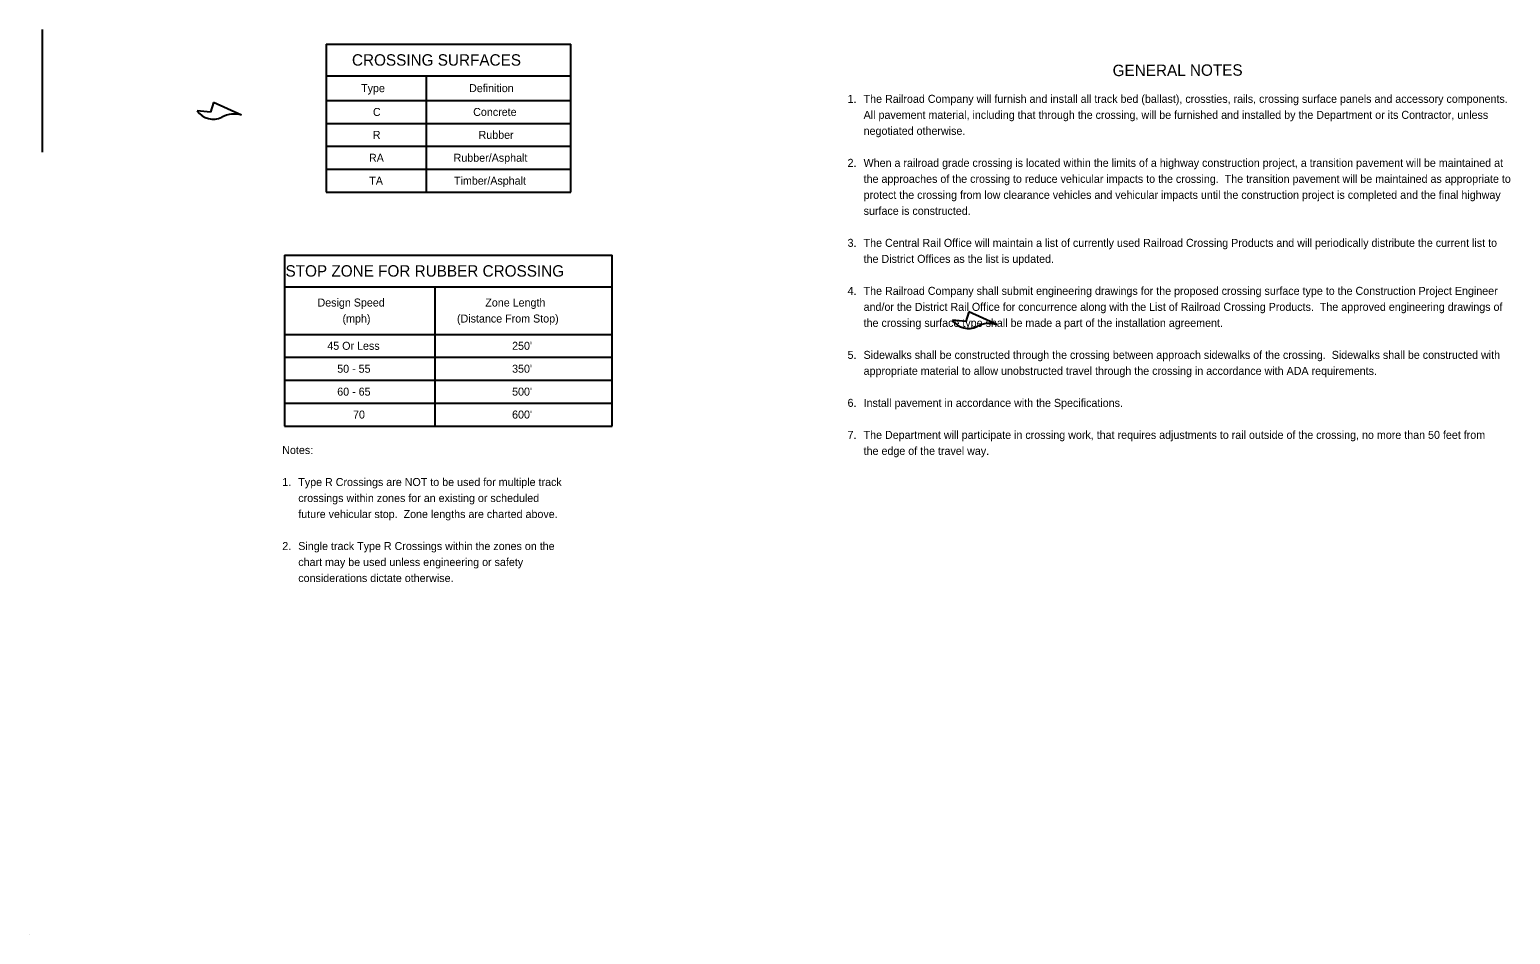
# Model space of a CAD drawing. Extents: x 10000 to 10648, y 10000 to 10396.
import ezdxf

# ---------------------------------------------------------------- set-up
doc = ezdxf.new("R2010")
doc.units = 0
for name, color, linetype in [('Default', 7, 'Continuous'), ('Dimension', 7, 'Continuous'), ('Patterning', 7, 'Continuous'), ('SupstrConc', 7, 'Continuous'), ('TextMisc', 7, 'Continuous')]:
    doc.layers.add(name, color=color, linetype=linetype)

msp = doc.modelspace()

# ---------------------------------------------------------------- linework, layer by layer
at = {"layer": 'Default'}
msp.add_line((10000, 10000), (10000, 10000), dxfattribs=at)
msp.add_line((10000, 10000), (10000, 10000), dxfattribs=at)
msp.add_line((10000, 10000), (10000, 10000), dxfattribs=at)
msp.add_line((10000, 10000), (10000, 10000), dxfattribs=at)
msp.add_line((10000, 10000), (10000, 10000), dxfattribs=at)
msp.add_line((10000, 10000), (10000, 10000), dxfattribs=at)
msp.add_line((10000, 10000), (10000, 10000), dxfattribs=at)
msp.add_line((10000, 10000), (10000, 10000), dxfattribs=at)
msp.add_line((10000, 10000), (10000, 10000), dxfattribs=at)
msp.add_line((10000, 10000), (10000, 10000), dxfattribs=at)
msp.add_line((10000, 10000), (10000, 10000), dxfattribs=at)
msp.add_line((10000, 10000), (10000, 10000), dxfattribs=at)
msp.add_line((10000, 10000), (10000, 10000), dxfattribs=at)
msp.add_line((10000, 10000), (10000, 10000), dxfattribs=at)
msp.add_line((10000, 10000), (10000, 10000), dxfattribs=at)
msp.add_line((10000, 10000), (10000, 10000), dxfattribs=at)
msp.add_line((10000, 10000), (10000, 10000), dxfattribs=at)
msp.add_line((10000, 10000), (10000, 10000), dxfattribs=at)
msp.add_line((10000, 10000), (10000, 10000), dxfattribs=at)
msp.add_line((10000, 10000), (10000, 10000), dxfattribs=at)
msp.add_line((10000, 10000), (10000, 10000), dxfattribs=at)
at = {"layer": 'Dimension'}
for p, q in [((10080.45, 10363.99), (10079.11, 10359.65)), ((10092.65, 10358.31), (10080.45, 10363.99)), ((10079.11, 10359.65), (10073.32, 10360.29)), ((10410.8, 10272.41), (10409.46, 10268.06)), ((10422.99, 10266.73), (10410.8, 10272.41)), ((10409.46, 10268.06), (10403.67, 10268.7))]:
    msp.add_line(p, q, dxfattribs=at)
for centre, radius, start, end in [((10080.41, 10365.34), 8.7, 215.52054, 295.31839), ((10089.31, 10348.47), 10.39, 71.2682, 119.91924), ((10410.75, 10273.76), 8.7, 215.52054, 295.31839), ((10419.66, 10256.88), 10.39, 71.2682, 119.91924)]:
    msp.add_arc(centre, radius, start, end, dxfattribs=at)
at = {"layer": 'Patterning'}
msp.add_line((10000, 10000), (10000, 10000), dxfattribs=at)
at = {"layer": 'SupstrConc'}
for p, q in [((10129.64, 10389.45), (10129.64, 10324.71)), ((10129.64, 10389.45), (10236.63, 10389.45)), ((10236.63, 10324.74), (10236.63, 10389.45)), ((10129.64, 10375.62), (10173.64, 10375.62)), ((10173.64, 10324.71), (10173.64, 10375.62)), ((10173.64, 10375.62), (10236.63, 10375.62)), ((10129.64, 10364.78), (10236.63, 10364.78)), ((10129.64, 10354.78), (10236.63, 10354.78)), ((10129.64, 10344.76), (10236.63, 10344.76)), ((10129.64, 10334.73), (10236.63, 10334.73)), ((10129.64, 10324.71), (10236.63, 10324.71)), ((10111.52, 10297.16), (10111.52, 10222.39)), ((10111.52, 10297.16), (10254.74, 10297.16)), ((10254.74, 10222.39), (10254.74, 10297.16)), ((10111.52, 10283.33), (10177.36, 10283.33)), ((10177.36, 10283.33), (10254.74, 10283.33)), ((10177.36, 10222.39), (10177.36, 10283.33)), ((10111.52, 10262.49), (10254.74, 10262.49)), ((10111.52, 10252.47), (10254.74, 10252.47)), ((10111.52, 10242.44), (10254.74, 10242.44)), ((10111.52, 10232.42), (10254.74, 10232.42)), ((10111.52, 10222.39), (10254.74, 10222.39))]:
    msp.add_line(p, q, dxfattribs=at)
at = {"layer": 'TextMisc'}
msp.add_line((10005.67, 10342.13), (10005.67, 10395.81), dxfattribs=at)

# ---------------------------------------------------------------- texts
for s, height, p in [('CROSSING SURFACES', 5, (10140.98, 10380.03)), ('Type', 3.5, (10144.98, 10368.45)), ('Definition', 3.5, (10192.19, 10368.45)), ('1.', 3.5, (10357.73, 10363.77)), ('The Railroad Company will furnish and install all track bed (ballast), crossties, rails, crossing surface panels and accessory components.  ', 3.5, (10364.73, 10363.77)), ('C', 3.5, (10150.15, 10358.03)), ('Concrete', 3.5, (10193.99, 10358.03)), ('All pavement material, including that through the crossing, will be furnished and installed by the Department or its Contractor, unless ', 3.5, (10364.75, 10356.77)), ('R', 3.5, (10150.07, 10348.02)), ('Rubber', 3.5, (10196.34, 10348.02)), ('negotiated otherwise.   ', 3.5, (10364.75, 10349.77)), ('RA', 3.5, (10148.42, 10338)), ('Rubber/Asphalt', 3.5, (10185.43, 10338)), ('2.', 3.5, (10357.73, 10335.77)), ('When a railroad grade crossing is located within the limits of a highway construction project, a transition pavement will be maintained at ', 3.5, (10364.73, 10335.77)), ('TA', 3.5, (10148.54, 10327.97)), ('Timber/Asphalt', 3.5, (10185.61, 10327.97)), ('the approaches of the crossing to reduce vehicular impacts to the crossing.  The transition pavement will be maintained as appropriate to ', 3.5, (10364.75, 10328.77)), ('protect the crossing from low clearance vehicles and vehicular impacts until the construction project is completed and the final highway ', 3.5, (10364.75, 10321.77)), ('surface is constructed.  ', 3.5, (10364.75, 10314.77)), ('3.', 3.5, (10357.73, 10300.77)), ('The Central Rail Office will maintain a list of currently used Railroad Crossing Products and will periodically distribute the current list to ', 3.5, (10364.73, 10300.77)), ('the District Offices as the list is updated.   ', 3.5, (10364.75, 10293.77)), ('STOP ZONE FOR RUBBER CROSSING', 5, (10111.92, 10287.74)), ('Design Speed', 3.5, (10125.91, 10274.66)), ('Zone Length', 3.5, (10199.29, 10274.66)), ('4.', 3.5, (10357.73, 10279.77)), ('The Railroad Company shall submit engineering drawings for the proposed crossing surface type to the Construction Project Engineer ', 3.5, (10364.73, 10279.77)), ('(mph)', 3.5, (10136.85, 10267.66)), ('(Distance From Stop)', 3.5, (10186.9, 10267.66)), ('and/or the District Rail Office for concurrence along with the List of Railroad Crossing Products.  The approved engineering drawings of ', 3.5, (10364.75, 10272.77)), ('the crossing surface type shall be made a part of the installation agreement.   ', 3.5, (10364.75, 10265.77)), ('45 Or Less', 3.5, (10130.19, 10255.73)), ("250'", 3.5, (10211.01, 10255.73)), ('5.', 3.5, (10357.73, 10251.77)), ('Sidewalks shall be constructed through the crossing between approach sidewalks of the crossing.  Sidewalks shall be constructed with ', 3.5, (10364.73, 10251.77)), ('50 - 55', 3.5, (10134.53, 10245.7)), ("350'", 3.5, (10211.01, 10245.7)), ('appropriate material to allow unobstructed travel through the crossing in accordance with ADA requirements.   ', 3.5, (10364.75, 10244.77)), ('60 - 65', 3.5, (10134.53, 10235.68)), ("500'", 3.5, (10211.01, 10235.68)), ('6.', 3.5, (10357.73, 10230.77)), ('Install pavement in accordance with the Specifications. ', 3.5, (10364.73, 10230.77)), ('70', 3.5, (10141.44, 10225.65)), ("600'", 3.5, (10211.01, 10225.65)), ('7.', 3.5, (10357.73, 10216.77)), ('The Department will participate in crossing work, that requires adjustments to rail outside of the crossing, no more than 50 feet from ', 3.5, (10364.73, 10216.77)), ('Notes:', 3.5, (10110.49, 10210.14)), ('the edge of the travel way.', 3.5, (10364.75, 10209.77)), ('1.', 3.5, (10110.49, 10196.14)), ('Type R Crossings are NOT to be used for multiple track ', 3.5, (10117.49, 10196.14)), ('crossings within zones for an existing or scheduled ', 3.5, (10117.5, 10189.14)), ('future vehicular stop.  Zone lengths are charted above.', 3.5, (10117.5, 10182.14)), ('2.', 3.5, (10110.49, 10168.14)), ('Single track Type R Crossings within the zones on the ', 3.5, (10117.49, 10168.14)), ('chart may be used unless engineering or safety ', 3.5, (10117.5, 10161.14)), ('considerations dictate otherwise. ', 3.5, (10117.5, 10154.14))]:
    msp.add_text(s, height=height, dxfattribs=at).set_placement(p)
msp.add_text('GENERAL NOTES', height=5, rotation=0.1969, dxfattribs=at).set_placement((10473.66, 10375.45))

doc.saveas('drawing.dxf')
